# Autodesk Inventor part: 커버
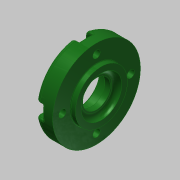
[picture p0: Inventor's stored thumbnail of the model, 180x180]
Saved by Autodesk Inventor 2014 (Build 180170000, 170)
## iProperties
Created: 2015-11
Part Number: 커버
Material: 알루미늄 6061
Document SubType Name: Modeling
Designer: mduedu
Density: 2.71 g/cm^3
Mass: 53.4178 g
Surface Area: 74.0957 cm^2
Volume: 19.7114 cm^3
Appearance: 매끄러움 - 짙은 산림 녹색
Author: mduedu
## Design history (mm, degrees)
sketch "스케치1"
  geometry: L1 (-7, 0)-(7, 0); L2 (-7, 0)-(-7, 27); L3 (-7, 27)-(4, 27); L4 (4, 27)-(4, 16); L5 (4, 16)-(7, 16); L6 (7, 16)-(7, 0); 2 further points
  constraints: 12 end point, 3 perpendicular, 2 parallel, 1 coincident, 1 horizontal, 1 midpoint
  dimensions: "d0" = 14 distance of L1.start L1.end; "d1" = 54 diameter of L3 L1; "d2" = 3 distance of L4.end L5.end; "d3" = 32 diameter of L5 L1
revolve "회전1" sketch "스케치1" stored, may be unused: angle "d4" = 90 deg
hole "구멍1" diameter "d7" = 25; stored, may be unused: countersink angle "d11" = 90 deg, drill point angle "d13" = 0 deg; dims "d5" = 10, "d6" = 10, "d8" = 6, "d9" = 4, "d10" = 2, "d12" = 3
hole "구멍2" diameter "d16" = 25; stored, may be unused: countersink angle "d20" = 90 deg, drill point angle "d22" = 0 deg; dims "d17" = 6, "d18" = 4, "d19" = 2, "d21" = 7.7, "d58" = 10, "d59" = 10
hole "구멍3" diameter "d25" = 17; stored, may be unused: countersink angle "d29" = 90 deg, drill point angle "d31" = 0 deg; dims "d23" = 10, "d24" = 10, "d26" = 6, "d27" = 4, "d28" = 2, "d30" = 4.2
chamfer "모따기1" distance "d32" = 0.6; stored, may be unused: second distance "d33" = 2, angle "d34" = 30 deg
fillet "모깎기1" dims "d35" = 0.3
fillet "모깎기2" dims "d36" = 3
fillet "모깎기3" dims "d37" = 3
fillet "모깎기4" dims "d38" = 0.3
sketch "스케치3" dims "d61" = 42
  geometry: C1 r 27 at (0, 0) reference; 2 further points
  constraints: 2 vertical alignment, 1 coincident, 2 other
hole "구멍4" sketch "스케치3" at (0, 21) diameter "d44" = 4.5; stored, may be unused: countersink angle "d48" = 90 deg, drill point angle "d50" = 0 deg; dims "d45" = 6, "d46" = 8, "d47" = 4.6, "d49" = 8
sketch "스케치4"
  geometry: L1 (-4, 5.702)-(-4, 0); L2 (4, 5.702)-(4, 0); A1 r 27 centre (0, -21) between (-4, 5.702) and (4, 5.702) reference; A2 r 4 centre (0, 0) between (-2.824, 2.833) and (2.824, 2.833) reference
  constraints: 4 end point, 4 point on circle, 2 tangent, 2 vertical
extrude "돌출1" cut sketch "스케치4" stored distance "d51" = 0; taper "d52" = 0 deg
fillet "모깎기5" dims "d56" = 0.3
fillet "모깎기6" dims "d57" = 1
node "솔리드1"
pattern_circular "원형 패턴2" dims angle "d64" = 360 deg
pattern_circular "원형 패턴1" dims angle "d54" = 360 deg
